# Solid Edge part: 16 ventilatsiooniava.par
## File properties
Author: Henri
Template: Normal.par
Last saved by: Henri
Revision: 3
Application: Solid Edge
Accuracy: 0,990
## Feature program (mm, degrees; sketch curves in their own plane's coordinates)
sketch for "unnamed Protrusion 1" plane through (0, 0, 0) normal (1, 0, 0) x-axis (0, 1, 0)
  line (0, 0) -> (0, 0)
  line (-6.5, 4) -> (6.5, 4)
  line (6.5, 4) -> (6.5, -4)
  line (6.5, -4) -> (-6.5, -4)
  line (-6.5, -4) -> (-6.5, 4)
extrude "unnamed Protrusion 1" add finite 5 along +normal
sketch for "ExtrudedProtrusion_2" plane through (0, 0, 0) normal (1, 0, 0) x-axis (0, 1, 0)
  line (-7.5, 5) -> (7.5, 5)
  line (7.5, 5) -> (7.5, -5)
  line (7.5, -5) -> (-7.5, -5)
  line (-7.5, -5) -> (-7.5, 5)
extrude "ExtrudedProtrusion_2" add finite 0.25 along -normal
thinwall "Thinwall_2"  Thickness = 0.25 mm
sketch for "unnamed Cutout 1" plane through (0, 0, 0) normal (1, 0, 0) x-axis (0, 1, 0)
  line (6.5, -4) -> (-6.5, -4)
  line (-6.5, -4) -> (-6.5, 4)
  line (-6.5, 4) -> (6.5, 4)
  line (6.5, 4) -> (6.5, -4)
extrude "unnamed Cutout 1" cut through along -normal
sketch for "ExtrudedProtrusion_3" plane through (2.5, 6.5, 0) normal (0, -1, 0) x-axis (1, 0, 0)
  circle centre (-2, 3.93) radius 0.025
extrude "ExtrudedProtrusion_3" add finite 13 along +normal
pattern "PatternOccurrence_1" of "ExtrudedProtrusion_3"  XDirCount = 6; XDirSpacing = 0.3 mm
pattern "unnamed Pattern 1"
sketch for "ExtrudedProtrusion_4" plane through (2.5, 0, -4) normal (0, 0, 1) x-axis (0, 1, 0)
  circle centre (-6.43, 2) radius 0.025
extrude "ExtrudedProtrusion_4" add finite 8 along +normal
pattern "PatternOccurrence_2" of "ExtrudedProtrusion_4"  XDirCount = 6; XDirSpacing = 0.3 mm
pattern "unnamed Pattern 2"
fillet "Round_2" radius 0.25
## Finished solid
Body 1: solid body, 2429 faces, 4868 edges, 2374 vertices.
  Faces by surface: cylinder 2400, plane 25, sphere 4
  Edges by curve: ellipse 4644, circle 156, line 68
Bounding box of the edges (mm; curved faces can reach further): 5.500 x 15.500 x 10.500, from (-0.5, -7.75, -5.25) to (5, 7.75, 5.25).
Cylindrical faces by radius (mm): R0.025 x2392, R0.25 x8
Spherical faces by radius (mm): R0.25 x4
Planar faces by outward normal: +x 3, +y 5, +z 5, -x 2, -y 5, -z 5
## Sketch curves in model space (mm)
circle centre (0.5, -6.43, -4) radius 0.025
line (0.5, 6.43, -4) -> (0.5, -6.43, -4)
circle centre (0.5, 6.5, 3.93) radius 0.025
line (0.5, 6.5, 3.93) -> (0.5, 6.5, -3.93)
line (0, 7.5, 5) -> (0, 7.5, -5)
line (0, 7.5, -5) -> (0, -7.5, -5)
line (0, -7.5, -5) -> (0, -7.5, 5)
line (0, -7.5, 5) -> (0, 7.5, 5)
line (0, 6.5, 4) -> (0, 6.5, -4)
line (0, 6.5, -4) -> (0, -6.5, -4)
line (0, -6.5, -4) -> (0, -6.5, 4)
line (0, -6.5, 4) -> (0, 6.5, 4)
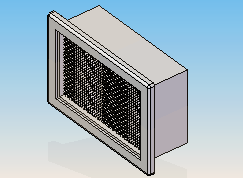
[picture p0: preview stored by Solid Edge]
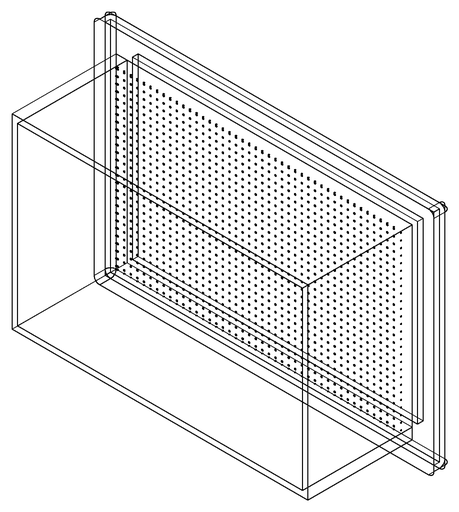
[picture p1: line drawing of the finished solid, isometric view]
